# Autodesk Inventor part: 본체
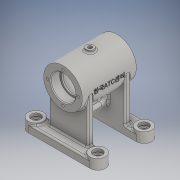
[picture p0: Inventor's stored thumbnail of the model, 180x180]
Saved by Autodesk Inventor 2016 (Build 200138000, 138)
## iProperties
Created: 2015-11
Part Number: 본체
Material: Generic
Document SubType Name: Modeling
Designer: Administrator
Density: 1 g/cm^3
Appearance: Default
Author: Administrator
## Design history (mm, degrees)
sketch "스케치2"
  geometry: L1 (-40, 40)-(40, 40); L2 (40, 20)-(-40, 20); L3 (63.121, 0)-(-63.121, 0); L4 (-40, -40)-(40, -40); L5 (40, -20)-(-40, -20); A1 r 10 centre (-40, 30) between (-40, 40) and (-40, 20); A2 r 10 centre (40, 30) between (40, 20) and (40, 40); A3 r 10 centre (-40, -30) between (-40, -20) and (-40, -40); A4 r 10 centre (40, -30) between (40, -40) and (40, -20); 4 further points
  constraints: 10 end point, 8 point on circle, 7 symmetric about line, 4 centre point, 2 horizontal, 2 midpoint, 1 coincident, 1 horizontal alignment, 1 parallel, 1 tangent, 2 other
  dimensions: "d18" = 80 distance of A2.centre A1.centre; "d19" = 40 horizontal distance of point (0, 0) A1.centre; "d22" = 40 distance from line of point (0, 0) L1; "d23" = 20 distance between parallel lines of L2 L1; "d24" = 10 radius of A2; "d25" = 10 radius of A1
extrude "돌출1" new body sketch "스케치2" distance "d26" = 10; taper "d27" = 0 deg
sketch "스케치3"
  geometry: L1 (40, 40)-(-40, 40) reference; L2 (-40, 20)-(40, 20) reference; L3 (-78.132, 0)-(78.132, 0); L4 (-25, 20)-(-25, 28); L5 (-25, 28)-(25, 28); L6 (25, 28)-(25, 20); L7 (-40, 20)-(40, 20) reference; L8 (-25, 20)-(25, 20); L9 (-25, -20)-(-25, -28); L10 (-25, -28)-(25, -28); L11 (25, -28)-(25, -20); L12 (-25, -20)-(25, -20); L13 (40, -20)-(-40, -20) reference; A1 r 10 centre (-40, 30) between (-40, 40) and (-40, 20) reference; A2 r 10 centre (40, 30) between (40, 20) and (40, 40) reference; 4 further points
  constraints: 18 end point, 5 symmetric about line, 2 collinear, 2 midpoint, 2 perpendicular, 2 point on line, 1 coincident, 1 horizontal, 1 vertical, 1 vertical alignment
  dimensions: "d28" = 8 distance between parallel lines of L2 L5; "d29" = 50 distance between parallel lines of L4 L6
extrude "돌출2" join sketch "스케치3" distance "d30" = 58; taper "d31" = 0 deg
sketch "스케치4"
  geometry: L1 (-25, 20)-(-25, 28) reference; L2 (-25, 28)-(25, 28) reference; L3 (25, 28)-(25, 20) reference; L4 (25, 20)-(40, 20) reference; L5 (40, 40)-(-40, 40) reference; L6 (-40, 20)-(-25, 20) reference; C1 r 10 at (-40, 30); C2 r 10 at (40, 30); A1 r 10 centre (40, 30) between (40, 20) and (40, 40) reference; A2 r 10 centre (-40, 30) between (-40, 40) and (-40, 20) reference; 1 further point
  constraints: 2 centre point, 2 coincident
  dimensions: "d32" = 20 diameter of C1; "d33" = 20 diameter of C2
extrude "돌출3" join sketch "스케치4" distance "d34" = 3; taper "d35" = 0 deg
sketch "스케치8"
  geometry: C1 r 25 at (0, 68); 1 further point
  constraints: 1 centre point, 1 vertical alignment
  dimensions: "d48" = 50 diameter of C1; "d49" = 68 distance of point (0, 0) C1.centre
extrude "돌출6" join sketch "스케치8" stored distance "d50" = 70; taper "d51" = 0 deg
node "작업 평면2"
sketch "스케치9"
  geometry: C1 r 5 at (0, 0); 1 further point
  constraints: 1 centre point, 1 coincident
  dimensions: "d52" = 10 diameter of C1
extrude "돌출7" join sketch "스케치9" distance "d53" = 3; taper "d55" = 0 deg; dims "d54" = 14.5, "d56" = 0
sketch "스케치10"
  geometry: L1 (0, 68)-(0, 29.545); L2 (0, 68)-(15.822, 40.595); A1 r 25 centre (0, 68) between (-25, 68) and (25, 68) reference; 3 further points
  constraints: 4 end point, 1 midpoint, 1 point on circle, 1 point on line, 1 vertical, 1 vertical alignment
  dimensions: "d57" = 68 distance of point (0, 0) L1.start; "d58" = 30 deg angle of L1 L2
node "작업 평면3"
sketch "스케치13"
  geometry: L1 (10, 28)-(68, 28) reference; L2 (68, 20)-(68, 28) reference; L3 (10, 20)-(68, 20) reference; L4 (10, 28)-(10, 20) reference; L5 (10, -20)-(68, -20) reference; L6 (68, -28)-(68, -20) reference; L7 (10, -28)-(68, -28) reference; L8 (10, -20)-(10, -28) reference; L9 (45, 20)-(23, 20); L10 (23, 20)-(23, -20); L11 (23, -20)-(45, -20); L12 (45, -20)-(45, 20); L13 (33, 31.422)-(33, -31.422); L14 (0, 40)-(0, 20) reference; 4 further points
  constraints: 10 end point, 3 midpoint, 2 horizontal alignment, 2 parallel, 1 horizontal, 1 perpendicular, 1 vertical
  dimensions: "d70" = 22 distance of L10.end L11.end; "d71" = 40 distance of L9.end L10.end; "d72" = 12 distance between parallel lines of L13 L12; "d74" = 33 distance from line of L14 point (33, 0)
extrude "돌출9" join sketch "스케치13" stored distance "d75" = 8; taper "d76" = 0 deg
sketch "스케치14"
  geometry: L1 (-20, 23)-(-20, 43.322) reference; L2 (-20, 23)-(20, 23) reference; L3 (20, 43.322)-(20, 23) reference; L4 (-11.5, 36.5)-(11.5, 36.5); L5 (11.5, 29.5)-(-11.5, 29.5); L6 (-15.947, 33)-(15.947, 33); L7 (-20, 43.322)-(20, 43.322) reference; A1 r 3.5 centre (-11.5, 33) between (-11.5, 36.5) and (-11.5, 29.5); A2 r 3.5 centre (11.5, 33) between (11.5, 29.5) and (11.5, 36.5); 3 further points
  constraints: 6 end point, 4 point on circle, 2 centre point, 2 horizontal, 2 midpoint, 2 vertical alignment, 1 parallel, 1 point on line, 1 tangent
  dimensions: "d79" = 33 distance of point (0, 0) point (0, 33); "d82" = 23 distance of A2.centre A1.centre; "d83" = 3.5 radius of A2; "d84" = 7 distance between parallel lines of L5 L4; "d85" = 3.5 radius of A1; "d176" = 11.5 distance of A1.centre point (0, 33)
extrude "돌출10" cut sketch "스케치14" stored distance "d86" = 8; taper "d87" = 0 deg
fillet "모깎기1" dims "d88" = 3.5
sketch "스케치15"
  geometry: C1 r 10 at (0, 0) reference; C2 r 6 at (0, 0); 1 further point
  constraints: 1 centre point, 1 coincident
  dimensions: "d89" = 12 diameter of C2
extrude "돌출11" cut sketch "스케치15" distance "d90" = 4; taper "d91" = 0 deg
sketch "스케치16"
  geometry: C1 r 6 at (0, 0) reference; C2 r 3 at (0, 0); 1 further point
  constraints: 1 centre point, 1 coincident
  dimensions: "d92" = 6 diameter of C2
extrude "돌출12" cut sketch "스케치16" stored distance "d93" = 4; taper "d94" = 0 deg
fillet "모깎기2" dims "d95" = 0.3
chamfer "모따기1" distance "d96" = 1; stored, may be unused: second distance "d97" = 2, angle "d98" = 45 deg
sketch "스케치17"
  geometry: C1 r 10 at (-80, 60) reference; C2 r 10 at (0, 0) reference; C3 r 10 at (0, 60) reference; C4 r 6 at (-80, 60); C5 r 6 at (0, 60); C6 r 6 at (0, 0); 1 further point
  constraints: 3 centre point, 3 coincident
  dimensions: "d99" = 12 diameter of C4; "d100" = 12 diameter of C5; "d101" = 12 diameter of C6
extrude "돌출13" cut sketch "스케치17" distance "d102" = 4; taper "d103" = 0 deg
sketch "스케치18"
  geometry: C1 r 6 at (0, 0) reference; C2 r 6 at (80, 0) reference; C3 r 6 at (80, -60) reference; C4 r 3 at (0, 0); C5 r 3 at (80, 0); C6 r 3 at (80, -60); 1 further point
  constraints: 3 centre point, 3 coincident
  dimensions: "d104" = 6 diameter of C4; "d105" = 6 diameter of C5; "d106" = 6 diameter of C6
extrude "돌출14" cut sketch "스케치18" stored distance "d107" = 4; taper "d108" = 0 deg
fillet "모깎기3" dims "d109" = 0.3
chamfer "모따기2" distance "d110" = 1; stored, may be unused: second distance "d111" = 2, angle "d112" = 45 deg
sketch "스케치19"
  geometry: L1 (93, 35)-(43, 35) reference; L2 (68, 43.747)-(68, -47.981); L3 (84, 35)-(84, 23.3); L4 (83.7, 23)-(82, 23); L5 (82, 23)-(82, 21); L6 (82, 21)-(86, 21); L7 (89, 18)-(89, -18); L8 (86, -21)-(82, -21); L9 (82, -21)-(82, -23); L10 (82, -23)-(83.7, -23); L11 (84, -23.3)-(84, -35); L12 (43, -35)-(93, -35) reference; L13 (84, -35)-(68, -35); L14 (84, 35)-(68, 35); L15 (68, 35)-(68, -35); A1 r 3 centre (86, 18) between (89, 18) and (86, 21); A2 r 3 centre (86, -18) between (86, -21) and (89, -18); A3 r 0.3 centre (83.7, 23.3) between (83.7, 23) and (84, 23.3); A4 r 0.3 centre (83.7, -23.3) between (84, -23.3) and (83.7, -23); 3 further points
  constraints: 26 end point, 11 point on line, 8 point on circle, 8 tangent, 6 perpendicular, 4 centre point, 2 collinear, 2 equal radius, 2 midpoint, 2 vertical
  dimensions: "d113" = 12 distance of L3.start point (84, 23); "d114" = 42 distance between parallel lines of L8 L6; "d115" = 12 distance of point (84, -23) L11.end; "d116" = 32 diameter of L3 L2; "d117" = 28 diameter of L5 L2; "d118" = 42 diameter of L7 L2; "d119" = 3 radius of A1; "d120" = 0.3 radius of A3
revolve "회전1" sketch "스케치19" stored, may be unused: angle "d121" = 90 deg
chamfer "모따기3" distance "d122" = 1; stored, may be unused: second distance "d123" = 2, angle "d124" = 45 deg
sketch "스케치20" dims "d125" = 40
  geometry: C1 r 21 at (0, 0) reference; 6 further points
  constraints: 2 vertical alignment, 1 coincident, 7 other
  dimensions: "d128" = 360 deg dimension on C1.centre point (0, 20) (derived)
hole "구멍1" sketch "스케치20" at (0, 20), (-20, 0), (0, -20), (20, 0) diameter "d130" = 3.242; stored, may be unused: countersink angle "d134" = 90 deg, drill point angle "d136" = 118 deg; dims "d131" = 8, "d132" = 4, "d133" = 2, "d135" = 10
sketch "스케치21"
  geometry: 2 further points
  constraints: 1 coincident
hole "구멍2" sketch "스케치21" at (0, 0) diameter "d137" = 5.188; stored, may be unused: countersink angle "d141" = 90 deg, drill point angle "d143" = 118 deg; dims "d138" = 12, "d139" = 4, "d140" = 2, "d142" = 25.75
fillet "모깎기4" dims "d151" = 2
fillet "모깎기5" dims "d152" = 2
fillet "모깎기6" dims "d153" = 2
node "작업 평면5"
node "작업 평면6"
sketch "스케치25"
  geometry: L1 (25, -35)-(25, 35) reference; 2 further points
  constraints: 1 horizontal alignment, 1 other
  dimensions: "d157" = 25 distance from line of point (0, 0) L1
feature "엠보싱2" sketch "스케치25" dims "d158" = 0.5, "d159" = 0
sketch "스케치26"
  geometry: L1 (0, 68)-(0, -18.265); L2 (0, 68)-(-25.435, 23.946); C1 r 14 at (0, 68) reference; A1 r 25 centre (0, 68) between (-21.296, 54.905) and (-5.556, 43.625) reference; 2 further points
  constraints: 4 end point, 1 point on circle, 1 point on line, 1 vertical
  dimensions: "d160" = 30 deg angle of L1 L2
node "작업 평면7"
sketch "스케치27"
  geometry: L1 (-25, -35)-(-25, 35) reference; C1 r 5 at (0, 0); 1 further point
  constraints: 1 centre point, 1 horizontal alignment
  dimensions: "d161" = 10 diameter of C1; "d162" = 25 distance from line of C1.centre L1
extrude "돌출15" join sketch "스케치27" distance "d163" = 3; taper "d165" = 0 deg; dims "d164" = 1.5, "d166" = 0
fillet "모깎기7" dims "d167" = 2
sketch "스케치28"
  geometry: C1 r 5 at (0, 0) reference; 2 further points
  constraints: 1 coincident
hole "구멍4" sketch "스케치28" at (0, 0) diameter "d168" = 5.188; stored, may be unused: countersink angle "d172" = 90 deg, drill point angle "d174" = 118 deg; dims "d169" = 12, "d170" = 4, "d171" = 2, "d173" = 16
fillet "모깎기8" dims "d177" = 2
node "솔리드1"
mirror "대칭1"
mirror "대칭2"
node "투영된 루프1"
node "투영된 루프2"
node "투영된 루프4"
node "투영된 루프5"
node "투영된 루프6"
node "투영된 루프7"
node "투영된 루프8"
node "투영된 루프9"
node "투영된 루프10"
node "투영된 루프11"
node "투영된 루프12"
node "투영된 루프13"
node "투영된 루프14"
node "투영된 루프16"
